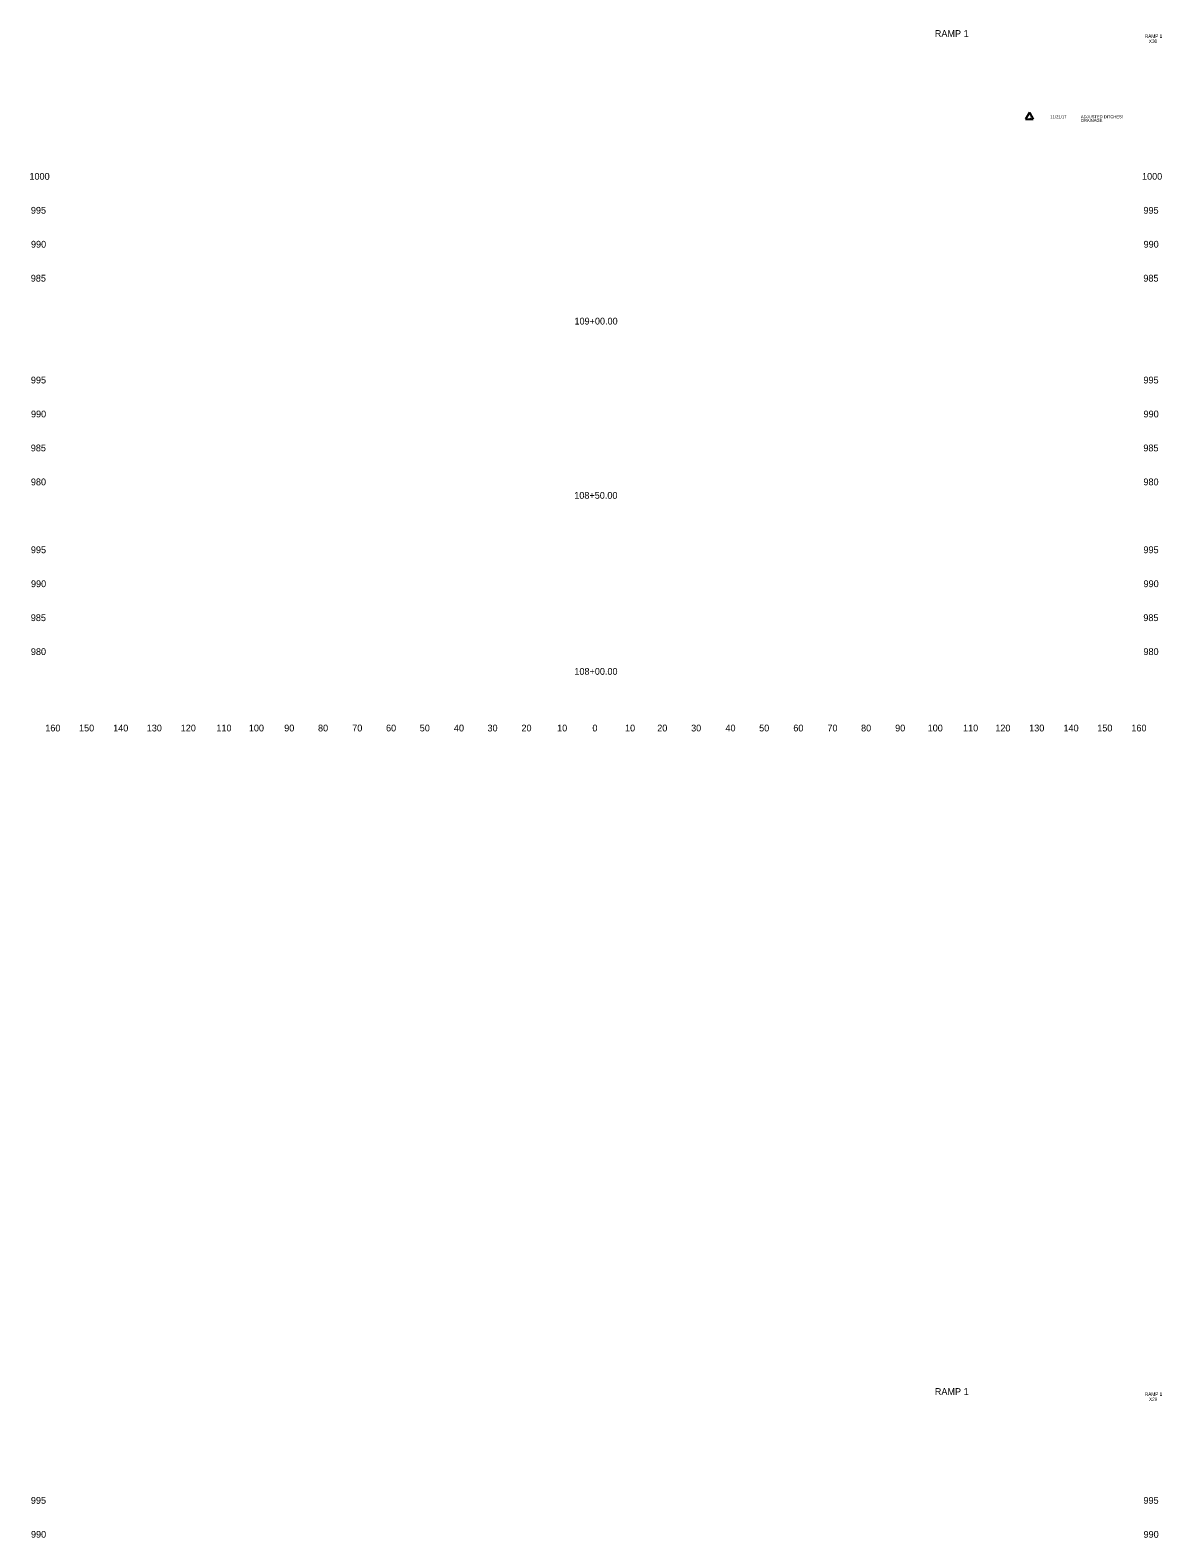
# Model space of a CAD drawing. Extents: x 4994 to 7869, y 4997 to 8804.
# Drawn here: x 6023.6 to 6357.1, y 8360 to 8804.1 of the extents above; entities that cross this region are included whole.
import ezdxf

# ---------------------------------------------------------------- set-up
doc = ezdxf.new("R2010")
doc.units = 0
for name, color, linetype in [('RD_SHT_ID', 7, 'Continuous'), ('RD_SHT_TX', 7, 'Continuous'), ('RD_XS_TX_Offset', 7, 'Continuous'), ('RD_XS_TX_Station', 7, 'Continuous')]:
    doc.layers.add(name, color=color, linetype=linetype)

msp = doc.modelspace()

# ---------------------------------------------------------------- linework, layer by layer
at = {"layer": 'RD_SHT_TX'}
for p, q in [((6318.05, 8779.83), (6316.91, 8777.8)), ((6318.05, 8779.83), (6319.19, 8777.8)), ((6316.91, 8777.8), (6319.19, 8777.8))]:
    msp.add_line(p, q, dxfattribs=at)

# ---------------------------------------------------------------- texts
at = {"layer": 'RD_SHT_ID'}
for s, height, p in [('RAMP 1', 2, (6290.19, 8802.06)), ('RAMP 1', 1, (6352.06, 8801.8)), ('X30', 1, (6353.25, 8800.3)), ('RAMP 1', 2, (6290.19, 8402.06)), ('RAMP 1', 1, (6352.06, 8401.8)), ('X29', 1, (6353.29, 8400.3))]:
    msp.add_text(s, height=height, dxfattribs=at).set_placement(p)
at = {"layer": 'RD_SHT_TX'}
for s, p in [('1', (6318.05, 8778.13)), ('11/21/17', (6324.24, 8778.09)), ('ADJUSTED DITCHES/', (6333.22, 8778.12)), ('DRAINAGE', (6333.22, 8777.02))]:
    msp.add_text(s, height=0.88, dxfattribs=at).set_placement(p)
at = {"layer": 'RD_XS_TX_Offset'}
for s, p in [('1000', (6023.44, 8760)), ('1000', (6351.24, 8760)), ('995', (6023.86, 8750)), ('995', (6351.66, 8750)), ('990', (6023.89, 8740)), ('990', (6351.69, 8740)), ('985', (6023.83, 8730)), ('985', (6351.63, 8730)), ('995', (6023.86, 8700)), ('995', (6351.66, 8700)), ('990', (6023.89, 8690)), ('990', (6351.69, 8690)), ('985', (6023.83, 8680)), ('985', (6351.63, 8680)), ('980', (6023.86, 8670)), ('980', (6351.66, 8670)), ('995', (6023.86, 8650)), ('995', (6351.66, 8650)), ('990', (6023.89, 8640)), ('990', (6351.69, 8640)), ('985', (6023.83, 8630)), ('985', (6351.63, 8630)), ('980', (6023.86, 8620)), ('980', (6351.66, 8620)), ('160', (6028.1, 8597.5)), ('150', (6038.04, 8597.5)), ('140', (6048.1, 8597.5)), ('130', (6057.99, 8597.5)), ('120', (6068.01, 8597.5)), ('110', (6078.51, 8597.5)), ('100', (6088.07, 8597.5)), ('90', (6098.5, 8597.5)), ('80', (6108.46, 8597.5)), ('70', (6118.54, 8597.5)), ('60', (6128.5, 8597.5)), ('50', (6138.43, 8597.5)), ('40', (6148.5, 8597.5)), ('30', (6158.39, 8597.5)), ('20', (6168.4, 8597.5)), ('10', (6178.91, 8597.5)), ('0', (6189.3, 8597.5)), ('0', (6189.3, 8597.5)), ('10', (6198.91, 8597.5)), ('20', (6208.4, 8597.5)), ('30', (6218.39, 8597.5)), ('40', (6228.5, 8597.5)), ('50', (6238.43, 8597.5)), ('60', (6248.5, 8597.5)), ('70', (6258.54, 8597.5)), ('80', (6268.46, 8597.5)), ('90', (6278.5, 8597.5)), ('100', (6288.07, 8597.5)), ('110', (6298.51, 8597.5)), ('120', (6308.01, 8597.5)), ('130', (6317.99, 8597.5)), ('140', (6328.1, 8597.5)), ('150', (6338.04, 8597.5)), ('160', (6348.1, 8597.5)), ('995', (6023.86, 8370)), ('995', (6351.66, 8370)), ('990', (6023.89, 8360)), ('990', (6351.69, 8360))]:
    msp.add_text(s, height=2, dxfattribs=at).set_placement(p)
at = {"layer": 'RD_XS_TX_Station'}
for s, p in [('109+00.00', (6184.02, 8717.35)), ('108+50.00', (6183.96, 8666.03)), ('108+00.00', (6183.99, 8614.18))]:
    msp.add_text(s, height=2, dxfattribs=at).set_placement(p)

doc.saveas('drawing.dxf')
